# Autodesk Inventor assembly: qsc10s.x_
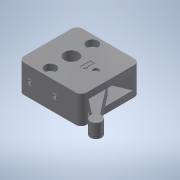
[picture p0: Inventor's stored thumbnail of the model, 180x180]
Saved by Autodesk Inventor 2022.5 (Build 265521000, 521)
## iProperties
Part Number: qsc10s.x_
Material: 一般
Document SubType Name: Assembly
Designer: ImaoCorp
Sending System: SOLIDWORKS 2017-2017317
MC: AMD64
MC_MODEL: Intel64 Family 6 Model 60 Stepping 3, GenuineIntel
OS: Windows_NT
FRU: Parasolid Version 29.0, build 201,  4-17-2017
FORMAT: text
GUISE: transmit
KEY: qsc10s
FILE: qsc10s.x_t
DATE: Wed Sep 04 15:35:46 2019
Author: ImaoCorp
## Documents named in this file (7)
- X:\14_SW2022-Inv2022\00_全2023-1023新製品(TCC)まで\q\qsc10s\QSC10S.iam
- X:\14_SW2022-Inv2022\00_全2023-1023新製品(TCC)まで\q\qsc10s\qsc10s_01.ipt
- X:\14_SW2022-Inv2022\00_全2023-1023新製品(TCC)まで\q\qsc10s\qsc10s_02.ipt
- X:\14_SW2022-Inv2022\00_全2023-1023新製品(TCC)まで\q\qsc10s\qsc10s_03.ipt
- X:\14_SW2022-Inv2022\00_全2023-1023新製品(TCC)まで\q\qsc10s\qsc10s_04.ipt
- X:\14_SW2022-Inv2022\00_全2023-1023新製品(TCC)まで\q\qsc10s\qsc10s_05.ipt
- X:\14_SW2022-Inv2022\00_全2023-1023新製品(TCC)まで\q\qsc10s\qsc10s_06.ipt
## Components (6 placed, 6 different names)
1. qsc10s_01
2. qsc10s_02
3. qsc10s_03
4. qsc10s_04
5. qsc10s_05
6. qsc10s_06
